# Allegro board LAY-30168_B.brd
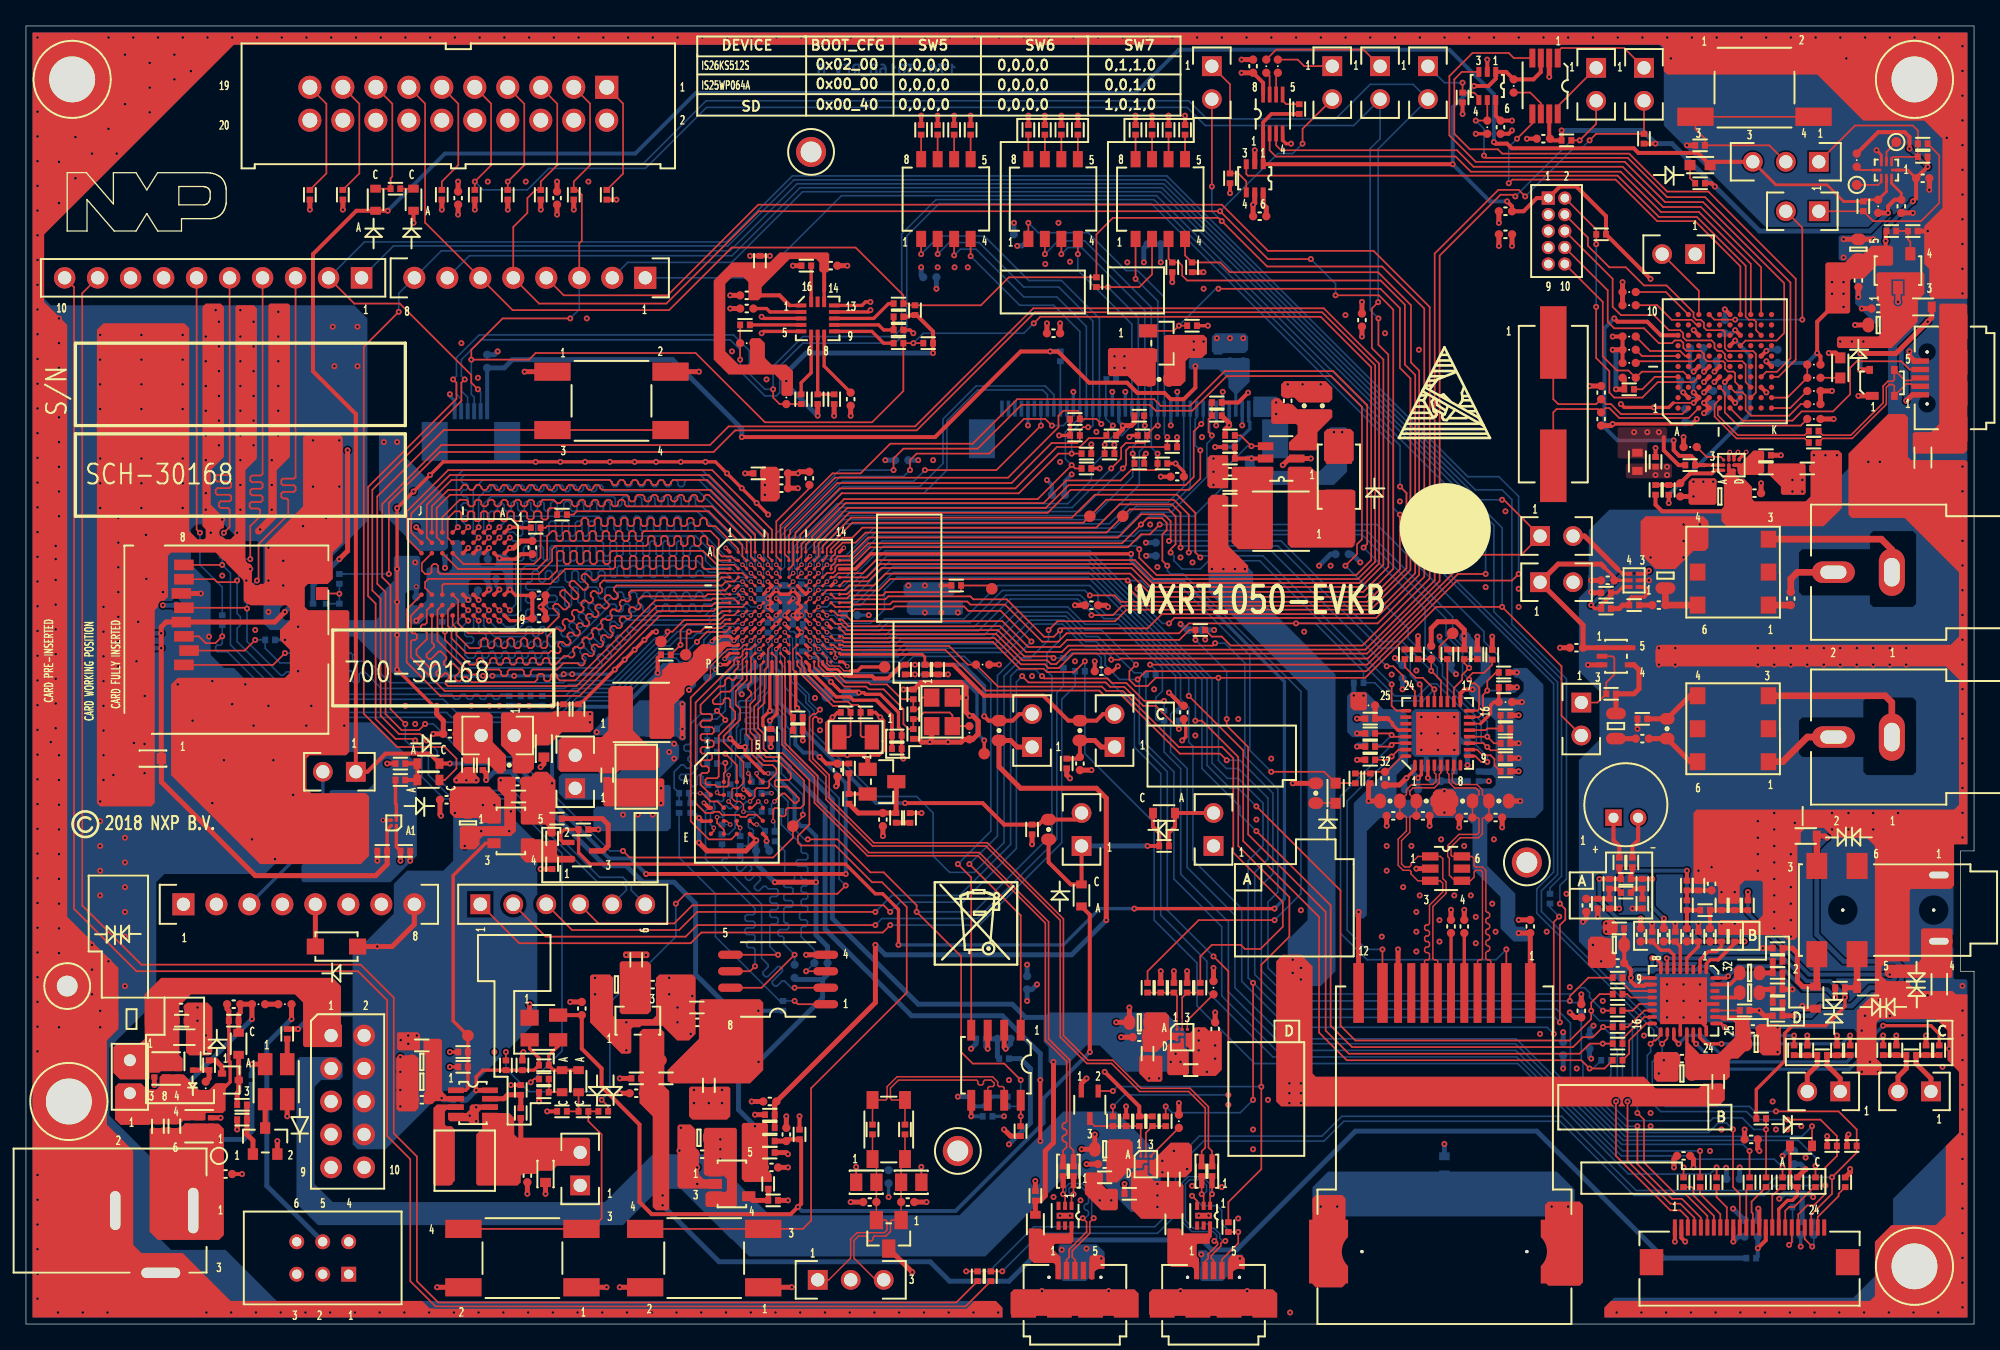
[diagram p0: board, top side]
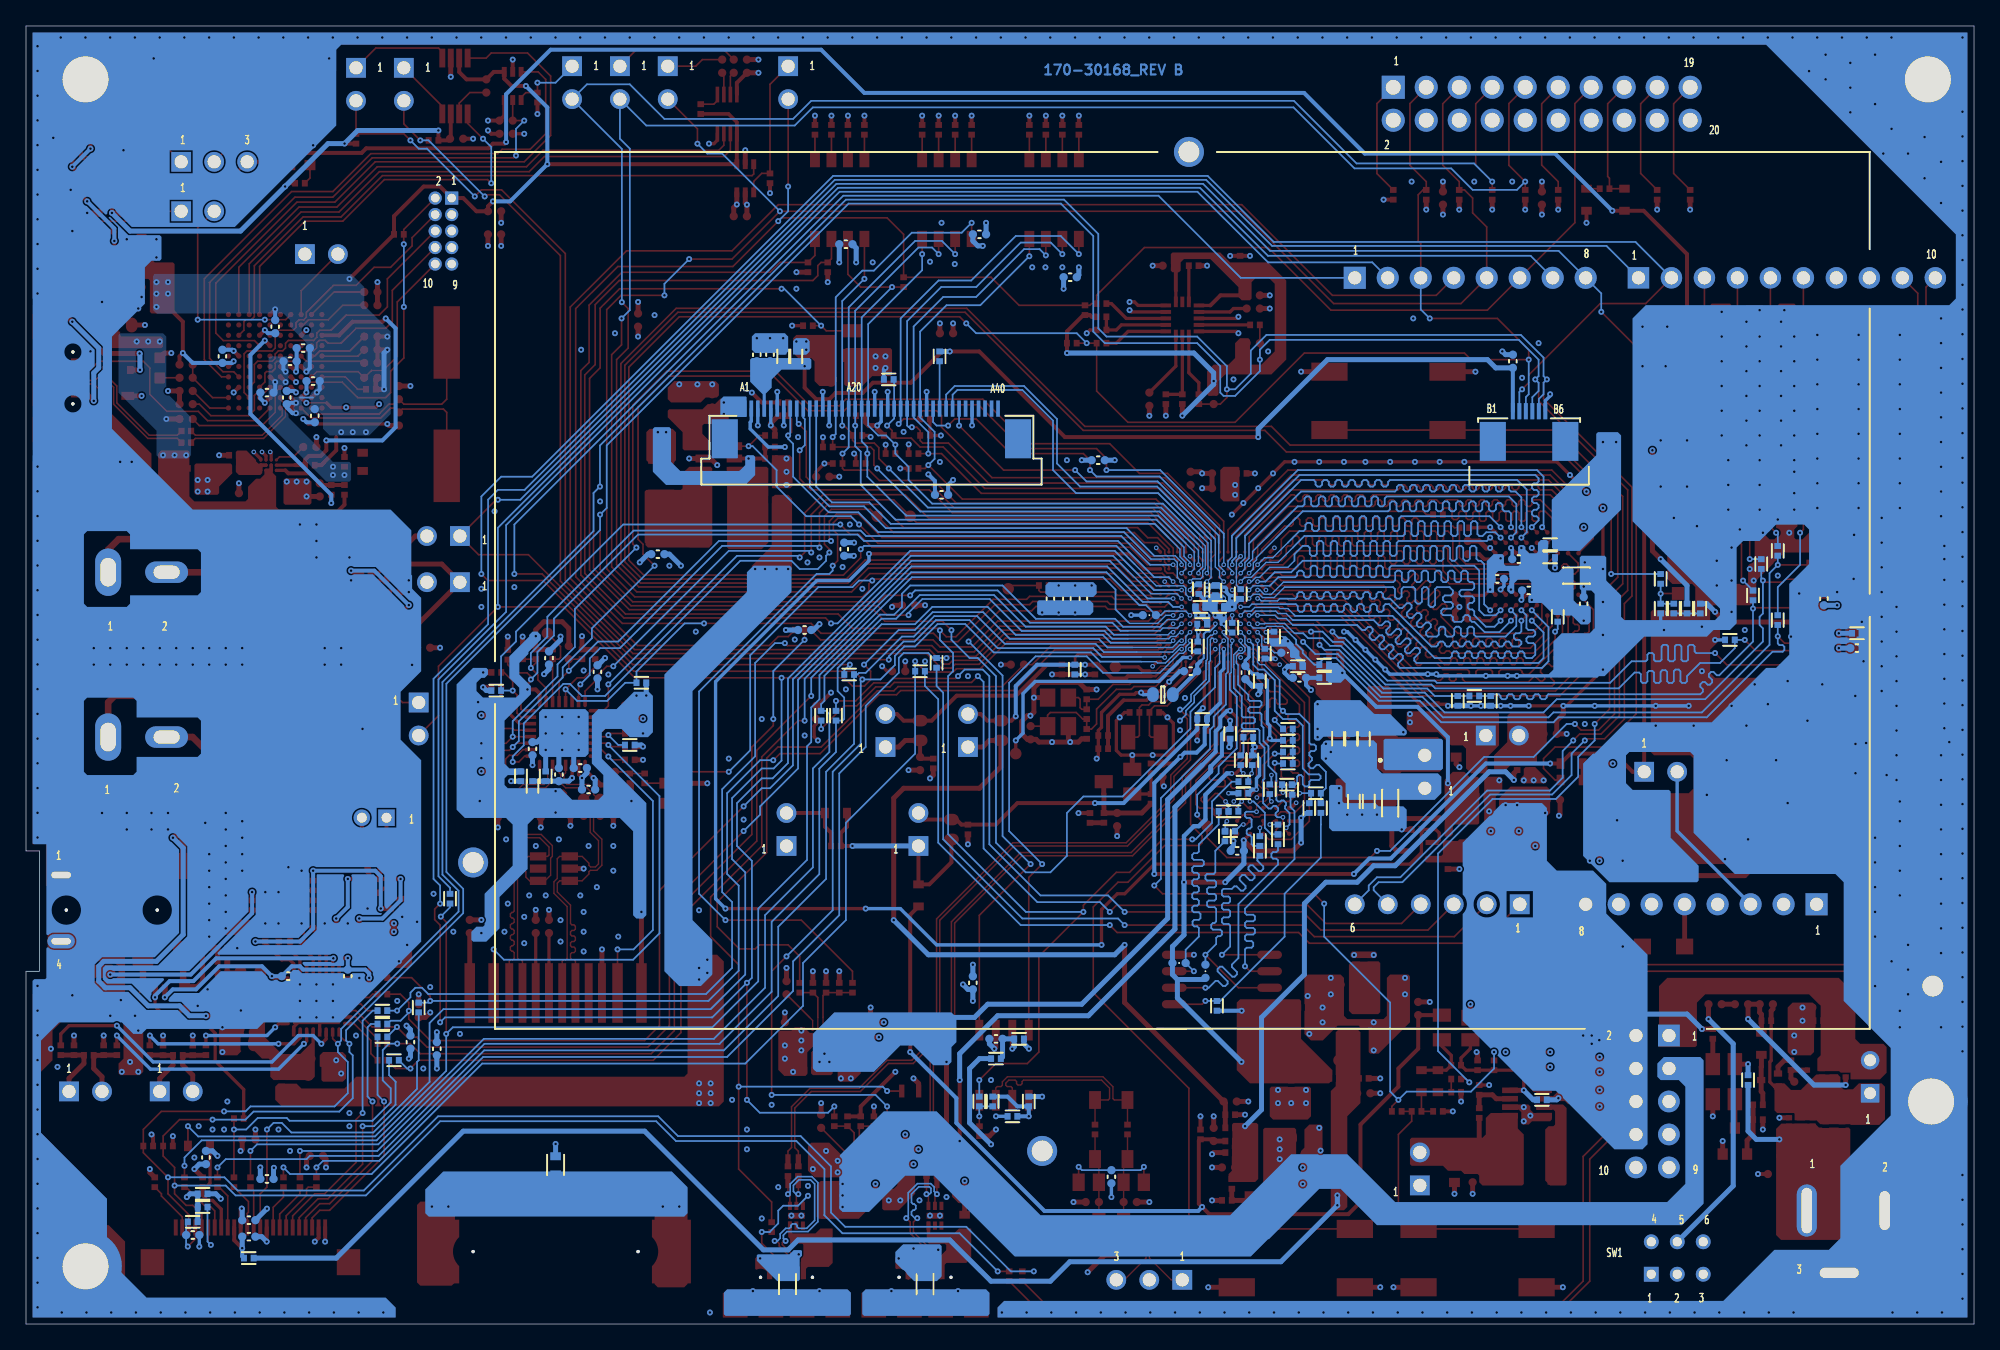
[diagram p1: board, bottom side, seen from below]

Outline 150 x 100 mm; copper layers: TOP, GND, INT1, BOTTOM. Coordinates in mm from the lower left corner of the outline.
Outline path: 0,100 150,100 150,36.45 148.97,36.45 148.97,27.18 150,27.18 150,0 0,0 0,100

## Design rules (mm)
net group CAN1_H: nets CAN1_H N101242461
net group CAN1_L: nets CAN1_L N101242463
net group ENET_RX: nets ENET_RXM ENET_RXP
net group ENET_TX: nets ENET_TXM ENET_TXP
net group FLEXSPI_DQS: nets FLEXSPI_DQS N101481296
net group GPIO_SD_B0_00: nets GPIO_SD_B0_00 N100763722
net group GPIO_SD_B0_02: nets GPIO_SD_B0_02 N100763684
net group GPIO_SD_B0_03: nets GPIO_SD_B0_03 N100763661
net group OTG1_DN: nets N99833038 OTG1_DN
net group OTG1_DP: nets N99833040 OTG1_DP
net group OTG2_DN: nets N99835007 OTG2_DN
net group OTG2_DP: nets N99835017 OTG2_DP
net group SDA_USB_CONN_DM: nets SDA_USB_CONN_DM SDA_USB_DM
net group SDA_USB_CONN_DP: nets SDA_USB_CONN_DP SDA_USB_DP
net group SEMC_CLK: nets N100763780 SEMC_CLK
net group 3W: nets AUD_INT CSI_MCLK CSI_PIXCLK ENET_INT ENET_RST ENET_TX_CLK JTAG_DACK JTAG_NSRST JTAG_RTCK JTAG_TCK LCDIF_CLK SDA_RST_LED SDA_RST_TGTMCU_J_B SW1_RST_B SWD_CLK_TGTMCU_BUF
net group FLEXSPI_CLK: nets FLEXSPI_CLK N100881534 N101474013
net group FLEXSPI_D0_A: nets FLEXSPI_D0_A N100881743 N101474117
net group FLEXSPI_D1_A: nets FLEXSPI_D1_A N100881750 N101474142
net group FLEXSPI_D2_A: nets FLEXSPI_D2_A N100881757 N101474197
net group FLEXSPI_D3_A: nets FLEXSPI_D3_A N100881764 N101474201
net group FLEXSPI_SS0: nets FLEXSPI_SS0 N100881537 N101351285
net group GND: nets GND
net group GPIO_SD_B0_01_B: nets GPIO_SD_B0_01_B N100763741 SD1_CLK
net group POWER: nets CAN_VIO_3V3 FLASH_VCC N99781633 N99781637 SDRAM_3V3 VDD_HIGH_IN_MCU VDD_USB_3V VDDA_ADC_3P3_MCU
net group SPI: nets FLEXSPI_CLK_B FLEXSPI_D0_B FLEXSPI_D1_B FLEXSPI_D2_B FLEXSPI_D3_B

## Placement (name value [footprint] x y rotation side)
C1  0.1UF  [CC0402_25]  11.94 24.38 0 top
C2  1.0UF  [0402_CC]  11.99 23.37 0 top
C3  47uF  [CC1206_OV]  8.13 23.5 180 top
C4  0.1UF  [CC0402_25]  15.37 11.56 0 top
C5  0.01UF  [CC0402_25]  16 24.64 0 top
C6  1.0UF  [0402_CC]  70.23 50.42 270 top
C7  0.22uF  [0402_CC]  69.22 50.42 270 top
C8  0.22uF  [0402_CC]  46.99 45.09 90 bottom
C9  0.22uF  [0402_CC]  58.12 55.24 0 bottom
C10  0.22uF  [0402_CC]  47.75 40.26 270 bottom
C11  0.22uF  [0402_CC]  58.42 56.52 270 bottom
C12  0.22uF  [0402_CC]  59.56 55.24 180 bottom
C13  4.7uF  [0402_CC]  56.46 56.24 90 bottom
C14  22UF  [0603_CC]  44.96 40.13 270 bottom
C15  4.7uF  [0402_CC]  67.69 50.42 270 top
C16  0.22uF  [0402_CC]  69.24 50.42 270 bottom
C17  0.22uF  [0402_CC]  47.96 45.09 90 bottom
C18  0.22uF  [0402_CC]  46.61 40.26 270 bottom
C19  0.22uF  [0402_CC]  59.44 53.92 0 bottom
C20  0.22uF  [0402_CC]  48.97 45.09 90 bottom
C21  0.22uF  [0402_CC]  59.44 45.72 0 top
C22  4.7uF  [0402_CC]  59.44 46.74 0 top
C23  0.22uF  [0402_CC]  77.47 38.1 270 top
C24  0.22uF  [0402_CC]  67.06 45.34 0 top
C25  0.22uF  [0402_CC]  59.77 52.2 90 bottom
C26  4.7uF  [0402_CC]  67.06 44.32 0 top
C27  0.1UF  [CC0402_25]  62.48 42.67 270 top
C29  0.1UF  [CC0402_25]  65.98 38.86 270 top
C30  1.0UF  [0402_CC]  27.43 36.45 180 top
C31  22UF  [0603_CC]  39.88 44.32 270 top
C32  4.7uF  [0402_CC]  52.07 50.67 0 bottom
C33  0.22uF  [0402_CC]  41.4 47.37 90 top
C34  0.22uF  [0402_CC]  42.55 47.37 90 top
C35  0.22uF  [0402_CC]  53.9 52.96 90 bottom
C36  33UF  [CC1210]  46.99 42.16 270 top
C37  0.22uF  [0402_CC]  44.75 42.29 270 top
C39  4.7PF  [0402_CC]  68.33 45.46 270 top
C40  4.7PF  [0402_CC]  68.33 48.51 90 top
C41  0.22uF  [0402_CC]  54.61 51.64 270 bottom
C42  10PF  [0402_CC]  64.64 47.12 0 top
C43  10PF  [0402_CC]  63.12 47.12 180 top
C44  10uF  [CC0603_OV]  30.48 20.19 180 top
C45  10uF  [CC0603_OV]  30.48 18.67 180 top
C46  0.1UF  [CC0402_25]  30.48 17.27 180 top
C47  22UF  [0603_CC]  40.01 11.56 270 top
C48  0.1UF  [CC0402_25]  38.61 11.43 270 top
C49  0.1UF  [CC0402_25]  58.55 14.61 90 top
C50  10uF  [CC0603_OV]  51.82 14.35 180 top
C51  0.1UF  [CC0402_25]  52.07 13.08 180 top
C52  4.7uF  [0402_CC]  57.27 13.21 0 top
C53  0.1UF  [CC0402_25]  57.4 12.06 0 top
C54  0.22uF  [0402_CC]  38.23 19.93 90 top
C55  1000pF  [0402_CC]  33.66 20.95 180 top
C56  1000pF  [0402_CC]  33.66 19.81 180 top
C57  0.1UF  [CC0402_25]  81.15 43.18 270 top
C58  1000pF  [0402_CC]  41.27 16.38 180 top
C59  0.1UF  [CC0402_25]  42.8 24.31 90 top
C60  1.0UF  [0402_CC]  39.88 18.87 0 top
C61  10uF  [CC0603_OV]  34.04 38.61 270 top
C62  0.1UF  [CC0402_25]  32.38 40.39 180 top
C63  4.7uF  [0402_CC]  37.92 40.64 180 top
C64  0.1UF  [CC0402_25]  37.85 41.78 180 top
C65  10uF  [CC0603_OV]  45.47 26.16 180 top
C66  0.1UF  [CC0402_25]  48.26 26.15 0 top
C67  4.7uF  [0402_CC]  46.99 18.92 180 top
C68  0.1UF  [CC0402_25]  46.99 17.78 180 top
C69  0.1UF  [CC0402_25]  58.17 64.39 0 top
C70  0.1UF  [CC0402_25]  58.17 65.53 0 top
C71  4.7uF  [0402_CC]  56.39 65.53 180 top
C72  4.7uF  [0402_CC]  59.69 56.62 270 bottom
C73  0.1UF  [CC0402_25]  71.12 55.88 90 bottom
C74  0.1UF  [CC0402_25]  69.85 55.88 90 bottom
C75  0.1UF  [CC0402_25]  68.58 55.88 90 bottom
C76  0.1UF  [CC0402_25]  60.33 65.15 90 top
C77  4.7uF  [0402_CC]  57.12 53.64 270 bottom
C78  0.1UF  [CC0402_25]  51.94 49.78 0 bottom
C79  1.0UF  [0402_CC]  57.28 45.47 270 bottom
C80  4.7uF  [0402_CC]  54.99 49.53 270 bottom
C81  0.1UF  [CC0402_25]  56.11 50.19 270 bottom
C82  10uF  [CC0603_OV]  62.46 48.49 0 bottom
C83  0.1UF  [CC0402_25]  60.33 50.29 0 bottom
C84  1.0UF  [0402_CC]  57.38 45.47 270 top
C85  4.7uF  [0402_CC]  91.69 74.55 90 bottom
C86  0.1UF  [CC0402_25]  93.73 74.68 90 bottom
C87  0.1UF  [CC0402_25]  92.71 74.68 90 bottom
C88  4.7uF  [0402_CC]  92.71 66.68 180 top
C89  4.7uF  [0402_CC]  92.71 64.64 180 top
C90  0.1UF  [CC0402_25]  92.71 65.66 180 top
C91  0.1UF  [CC0402_25]  97.16 71.12 90 top
C92  0.1UF  [CC0402_25]  35.51 74.17 90 bottom
C93  4.7uF  [0402_CC]  88.39 11.15 90 top
C97  4.7uF  [0402_CC]  77.72 9.88 90 top
C98  0.1UF  [CC0402_25]  75.31 21.97 0 bottom
C99  1.0UF  [0402_CC]  73.53 21.97 180 bottom
C100  1.0UF  [0402_CC]  74.04 16 0 bottom
C101  56PF  [CC0402_25]  64.97 9.4 0 top
C102  0.01UF  [CC0402_25]  66.42 11.35 270 bottom
C103  56PF  [CC0402_25]  67.89 9.4 0 top
C104  10uF  [CC0603_OV]  122.3 29.21 180 top
C105  0.1UF  [CC0402_25]  122.56 27.81 180 top
C106  0.1UF  [CC0402_25]  125.22 26.8 270 bottom
C107  0.1UF  [CC0402_25]  129.79 26.8 180 bottom
C108  10uF  [CC0603_OV]  127.51 19.3 180 top
C109  10uF  [CC0603_OV]  133.22 21.59 0 top
C110  0.1UF  [CC0402_25]  127.51 20.45 180 top
C111  0.1UF  [CC0402_25]  132.97 22.73 0 top
C112  4.7uF  [0402_CC]  131.57 29.84 90 top
C113  4.7uF  [0402_CC]  132.33 24.15 0 top
C114  220PF  [0402_CC]  134.87 28.96 0 top
C115  220PF  [0402_CC]  134.87 23.75 180 top
C116  4.7uF  [0402_CC]  121.03 32.38 270 top
C117  0.1UF  [CC0402_25]  120.14 32.25 270 top
C118  15PF  [0402_CC]  125.22 29.84 270 top
C119  4.7uF  [0402_CC]  128.78 33.78 90 top
C120  0.1UF  [CC0402_25]  129.79 33.92 90 top
C121  15PF  [0402_CC]  128.78 29.84 270 top
C122  0.1UF  [CC0402_25]  124.33 29.98 270 top
C123  0.1UF  [CC0402_25]  127.89 29.98 90 top
C124  4.7uF  [0402_CC]  123.19 33.24 0 top
C125  0.1UF  [CC0402_25]  129.67 29.98 90 top
C126  0.1UF  [CC0402_25]  126.11 29.98 270 top
C127  15PF  [0402_CC]  130.56 29.84 90 top
C128  15PF  [0402_CC]  130.56 32.26 90 top
C129  15PF  [0402_CC]  131.57 32.26 90 top
C130  15PF  [0402_CC]  127 29.84 90 top
C131  0.1UF  [CC0402_25]  135.89 55.89 270 top
C132  0.01UF  [CC0402_25]  125.73 55.38 180 top
C133  0.1UF  [CC0402_25]  121.79 57.29 180 top
C134  15PF  [0402_CC]  146.3 21.09 270 top
C135  15PF  [0402_CC]  139.45 21.08 270 top
C136  15PF  [0402_CC]  144.02 21.09 90 top
C137  15PF  [0402_CC]  137.16 21.08 90 top
C138  0.1UF  [CC0402_25]  119.39 52.1 180 top
C139  0.1UF  [CC0402_25]  124.46 45.1 0 top
C140  4.7uF  [0402_CC]  109.98 42.2 90 bottom
C141  0.1UF  [CC0402_25]  108.97 42.33 90 bottom
C142  2.2uF  [CC0402_25]  107.31 42.83 0 bottom
C143  0.1UF  [CC0402_25]  106.68 41.18 180 bottom
C144  10PF  [CC0402_25]  113.16 39.02 0 top
C145  10PF  [CC0402_25]  110.87 39.02 180 top
C146  10PF  [CC0402_25]  107.57 39.15 0 top
C147  10PF  [CC0402_25]  105.28 39.15 180 top
C148  0.1UF  [CC0402_25]  115.83 30.63 90 top
C149  0.1UF  [CC0402_25]  109.73 30.63 90 top
C150  0.1UF  [CC0402_25]  110.75 30.63 90 top
C160  4.7uF  [0402_CC]  9.02 53.21 180 bottom
C161  0.1UF  [CC0402_25]  9.02 52.07 180 bottom
C162  0.1UF  [CC0402_25]  56.73 36.45 0 bottom
C163  4.7uF  [0402_CC]  56.26 40.89 0 bottom
C164  4.7uF  [0402_CC]  32.64 59.05 180 bottom
C165  0.1UF  [CC0402_25]  38.99 59.82 90 top
C166  0.1UF  [CC0402_25]  35.05 58.93 0 bottom
C167  0.1UF  [CC0402_25]  39.5 56.13 0 top
C168  0.1UF  [CC0402_25]  36.7 57.4 180 bottom
C169  0.1UF  [CC0402_25]  39.5 54.36 0 top
C170  0.1UF  [CC0402_25]  34.29 56.52 0 bottom
C171  0.1UF  [CC0402_25]  30.06 55.5 90 bottom
C184  10uF  [CC0603_OV]  130.43 63.75 180 top
C185  0.1UF  [CC0402_25]  133.1 64.01 0 top
C186  0.1UF  [CC0402_25]  113.92 85.72 180 top
C187  0.1UF  [CC0402_25]  61.97 81.53 0 top
C188  0.1UF  [CC0402_25]  55.5 79.25 180 top
C189  0.1UF  [CC0402_25]  63.5 71.25 270 top
C190  0.1UF  [CC0402_25]  55.5 78.23 180 top
C191  1.0UF  [0402_CC]  51.66 24.38 180 top
C192  0.1UF  [CC0402_25]  51.69 23.24 180 top
C193  0.1UF  [CC0402_25]  111 44.32 90 bottom
C194  0.1UF  [CC0402_25]  120.4 21.72 90 bottom
C195  0.1UF  [CC0402_25]  118.36 21.21 90 bottom
C196  0.1UF  [CC0402_25]  119.76 24.13 90 top
C197  0.1UF  [CC0402_25]  90.04 53.47 180 bottom
C198  0.1UF  [CC0402_25]  82.8 50.29 0 top
C199  0.1UF  [CC0402_25]  89.15 47.12 270 top
C200  0.1UF  [CC0402_25]  91.57 22.73 270 top
C201  0.1UF  [CC0402_25]  77.09 26.29 270 bottom
C202  0.1UF  [CC0402_25]  131.44 11.18 180 bottom
C203  0.1UF  [CC0402_25]  127.64 12.95 180 top
C204  0.1UF  [CC0402_25]  132.84 14.22 0 top
C205  0.1UF  [CC0402_25]  136.14 12.83 90 bottom
C206  0.1UF  [CC0402_25]  113.92 83.95 0 top
C207  0.1UF  [CC0402_25]  40.89 86.74 270 top
C208  0.1UF  [CC0402_25]  102.87 77.34 270 top
C209  0.1UF  [CC0402_25]  33.27 86.74 270 top
C210  0.1UF  [CC0402_25]  109.73 51.31 270 bottom
C211  0.1UF  [CC0402_25]  105.99 50.24 270 bottom
C212  0.1UF  [CC0402_25]  82.04 55.37 0 top
C213  0.1UF  [CC0402_25]  76.58 83.95 180 bottom
C214  0.1UF  [CC0402_25]  69.6 80.64 180 bottom
C215  0.1UF  [CC0402_25]  86.87 83.19 180 bottom
C216  0.1UF  [CC0402_25]  79.12 76.33 180 top
C217  0.1UF  [CC0402_25]  101.35 59.31 0 bottom
C218  0.1UF  [CC0402_25]  67.44 66.55 180 bottom
C219  0.1UF  [CC0402_25]  87 59.69 90 bottom
C220  0.1UF  [CC0402_25]  88.65 65.28 0 top
C221  0.1UF  [CC0402_25]  79.5 63.88 180 bottom
C222  0.1UF  [CC0402_25]  11.56 55.88 90 bottom
C223  0.1UF  [CC0402_25]  32.64 45.47 180 top
C229  0.1UF  [CC0402_25]  57.28 17.14 180 top
C230  22UF  [CC0603_OV]  132.72 27.05 0 top
C231  22UF  [CC0603_OV]  132.72 25.53 0 top
C232  15PF  [0402_CC]  145.16 20.7 180 top
C233  15PF  [0402_CC]  138.3 20.7 180 top
C234  0.1UF  [CC0402_25]  104.65 42.04 270 top
C235  10uF  [CC0603_OV]  83.06 13.46 180 top
C236  0.1UF  [CC0402_25]  83.06 12.32 180 top
C237  10uF  [CC0603_OV]  85.72 23.24 180 top
C238  0.1UF  [CC0402_25]  85.72 22.1 180 top
C239  4.7uF  [0402_CC]  89.69 19.56 0 top
C240  4.7uF  [0402_CC]  84.96 10.03 180 top
C241  4.7uF  [0402_CC]  133.99 66.93 0 top
C242  22UF  [0603_CC]  9.78 43.56 180 top
C243  22UF  [0603_CC]  30.61 57.66 180 bottom
C244  18PF  [0402_CC]  39.75 48.01 270 bottom
C245  18PF  [0402_CC]  37.21 48.01 270 bottom
C246  0.1UF  [CC0402_25]  132.84 8 180 bottom
C247  0.1UF  [CC0402_25]  132.84 6.73 180 bottom
C248  0.1UF  [CC0402_25]  137.16 6.86 180 bottom
C249  4.7uF  [0402_CC]  136.4 10.03 180 bottom
C252  1.0UF  [0402_CC]  29.21 36.45 0 top
C254  0.1UF  [CC0402_25]  129.67 74.17 180 bottom
C255  10uF  [CC0603_OV]  141.1 82.8 90 top
C257  10uF  [CC0603_OV]  142.62 76.96 180 top
C258  4.7uF  [0402_CC]  125.48 66.42 90 top
C259  0.1UF  [CC0402_25]  142.62 78.23 180 top
C260  0.1UF  [CC0402_25]  141.1 80.39 270 top
C261  0.1UF  [CC0402_25]  131.44 71.75 0 bottom
C262  0.1UF  [CC0402_25]  127.89 72.64 0 bottom
C263  0.1UF  [CC0402_25]  134.87 74.55 90 bottom
C264  0.1UF  [CC0402_25]  130.81 76.83 270 bottom
C265  0.1UF  [CC0402_25]  129.92 71.37 90 bottom
C266  2.2uF  [CC0402_25]  128.65 75.18 0 bottom
C267  2.2uF  [CC0402_25]  127.76 69.98 270 bottom
C268  0.1UF  [CC0402_25]  144.4 86.11 270 top
C270  0.1UF  [CC0402_25]  146.05 88.27 0 top
C272  1000pF  [0402_CC]  128.91 90.81 180 top
C273  27PF  [CC0402_25]  121.28 69.72 270 top
C274  27PF  [CC0402_25]  121.28 71.75 90 top
C275  0.1UF  [CC0402_25]  116.84 91.31 180 top
C276  0.1UF  [CC0402_25]  113.54 92.2 270 top
C277  0.1UF  [CC0402_25]  94.49 96.9 90 top
C278  0.1UF  [CC0402_25]  95 85.34 180 top
D1  MM5Z5V1ST1G  [SOD_523_1P4]  12.83 20.26 90 top
D2  RB521S30  [SOD523]  16.37 21.59 270 top
D3  LED_RED-GRN  [LED_DUAL_3025MM_SM]  19.26 18.67 270 top
D4  RB521S30  [SOD523]  81.27 33.02 270 top
D5  RB521S30  [SOD523]  87.63 39.36 0 top
D6  RB521S30  [SOD523]  30.99 41.91 180 top
D7  RB521S30  [SOD523]  30.99 43.18 180 top
D8  RB521S30  [SOD523]  42.55 18.71 90 top
D9  RB521S30  [SOD523]  41.28 18.71 90 top
D10  MBRA160T3G  [CASE403D_02]  101.09 65.28 270 top
D11  NUP2105L  [SOT-23]  66.43 6.91 180 top
D12  RB521S30  [SOD523]  29.84 86.61 270 top
D13  RB521S30  [SOD523]  26.92 86.61 270 top
D14  MBR120VLSFT1G  [SOD-123]  23.91 29.08 180 top
D17  RB521S30  [SOD523]  136.68 13.72 180 top
D18  GREEN  [LED_0603]  100.84 40.89 90 top
D20  RED  [LED_0603]  139.7 73.66 90 top
D21  RED  [LED_0603]  128.91 89.28 0 top
FL1  ACT45B-510-2P  [IND4_4P7X3P4_SMT]  66.43 14.99 90 top
H1  .635" LONG  [SPACER_139T]  3.56 95.89 0 top
H2  .635" LONG  [SPACER_139T]  145.41 95.89 0 top
H3  .635" LONG  [SPACER_139T]  3.3 17.14 0 top
H4  .635" LONG  [SPACER_139T]  145.41 4.45 270 top
J1  HDR 2X5  [HDR205]  23.5 22.23 0 top
J2  CON_1_PWR  [CON3_PWR_TH]  12.88 8.74 270 top
J3  HDR 1X2  [HDR102]  83.82 44.45 180 top
J4  HDR 1X2  [HDR102]  77.47 44.45 180 top
J5  HDR 1X2  [HDR102]  81.28 36.83 180 top
J6  HDR 1X2  [HDR102]  91.44 36.83 180 top
J7  HDR 1X2  [HDR102]  42.67 10.68 180 top
J8  CON 1X40 + CON 1X6 + TFT DISPLAY  [MODULE_TOUCH_PANEL_46P]  60.96 56.52 180 bottom
J9  USB_MICROAB_RECEPTACLE  [CON_USB5_MICROAB_0P65_SM]  91.44 1.48 0 top
J10  USB_MICROAB_RECEPTACLE  [CON_USB5_MICROAB_0P65_SM]  80.77 1.48 0 top
J11  HDR_1X3  [HDR103]  60.97 3.4 90 top
J12  PJ31360-I  [CON6_AUDJACK_RA_TH]  147.3 34.59 180 top
J13  HDR 1X2  [HDR102]  116.59 57.15 90 top
J14  CON_2_RCA  [CON2_RCA_RA_TH]  143.67 57.92 180 top
J15  HDR 1X2  [HDR102]  116.59 60.71 90 top
J16  HDR 1X2  [HDR102]  146.69 17.92 270 top
J17  HDR 1X2  [HDR102]  139.7 17.92 270 top
J18  CON_2_RCA  [CON2_RCA_RA_TH]  143.67 45.22 180 top
J19  RJ45_YLW+GRN  [CON12_RJ45_1P02_SM]  109.22 15.54 180 top
J21  BH25420B301  [HDR_2X10M_100_TH]  44.72 95.28 270 top
J22  SKT_1X8  [CON_1X8_SKT_2P54_TH]  47.68 80.6 270 top
J23  SKT_1X6  [CON_SKT1X6_TH]  34.98 32.34 90 top
J24  SKT_1X10  [CON_SKT1X10_TH]  25.84 80.6 270 top
J25  SKT_1X8  [CON_1X8_SKT_2P54_TH]  12.12 32.34 90 top
J26  HDR 1X2  [HDR102]  25.4 42.55 270 top
J34  HDR 2X5  [HDR205_50_TH]  117.22 86.74 270 top
J35  CON_1X24  [FPC1X24_0P5_16P6X5P35]  132.72 4.26 0 top
J36  HDR 1X2  [HDR102]  42.29 41.27 180 top
J37  HDR 1X2  [HDR102]  37.59 45.34 270 top
J38  HDR 1X2  [HDR102]  119.76 47.88 0 top
J39  95220030-14RRF  [CON_SDCARD_95220]  15.43 52.72 90 top
J41  USB_MICROAB_RECEPTACLE  [CON_USB5_MICROAB_0P65_SM]  148.5 72.89 90 top
J42  HDR 1X2  [HDR102]  128.52 82.42 270 top
J43  HDR_1X3  [HDR103]  138.05 89.53 270 top
J44  HDR 1X2  [HDR102]  138.05 85.72 270 top
J45  HDR 1X2  [HDR102]  120.9 96.77 0 top
J46  HDR 1X2  [HDR102]  124.59 96.77 0 top
J47  HDR 1X2  [HDR102]  107.95 96.9 0 top
J48  HDR 1X2  [HDR102]  104.27 96.9 0 top
J49  HDR 1X2  [HDR102]  100.58 96.9 0 top
J50  HDR 1X2  [HDR102]  91.31 96.9 0 top
JP1  SHORT_100mil  [100MIL_TH]  8 17.78 90 top
L1  4.7uH  [IND_VLS4012E]  47.37 47.12 0 top
L2  1uH  [IND_4020]  33.78 12.59 0 top
L3  10uH  [IND_VLS4012E]  96.65 61.85 180 top
L4  330 OHM  [IND_1608]  88.39 7.72 90 top
L5  90OHM  [IND4_CHOKE_0805]  90.93 11.77 90 top
L6  330 OHM  [IND_1608]  91.36 3.1 90 bottom
L7  330 OHM  [IND_1608]  77.72 7.72 90 top
L8  90OHM  [IND4_CHOKE_0805]  80.26 11.77 90 top
L9  330 OHM  [IND_1608]  80.77 3.1 90 bottom
L10  120 Ohm  [0402_CC]  134.87 27.94 0 top
L11  120 Ohm  [0402_CC]  134.87 24.77 0 top
L12  120 Ohm  [0402_CC]  132.59 32.26 90 top
L13  120 Ohm  [0402_CC]  111 41.45 90 bottom
L14  330 OHM  [IND_1608]  109.22 12.22 270 bottom
L17  120 Ohm  [0402_CC]  140.08 10.92 90 top
L18  120 Ohm  [0402_CC]  32.64 60.07 0 bottom
L19  120 Ohm  [0402_CC]  137.16 7.87 180 bottom
L20  120 Ohm  [0402_CC]  132.84 5.08 0 bottom
L22  330 OHM  [IND_1608]  146.06 66.71 270 top
L23  330 OHM  [IND_1608]  146.05 78.36 180 top
L24  330 OHM  [IND_1608]  124.08 66.42 270 top
NOREF  -  []  10.38 3.94 0 top
NOREF#2  -  []  29.6 53.73 0 top
NOREF#3  -  []  62.46 75.97 90 top
NOREF#4  -  []  8.32 46.12 0 top
NOREF#5  -  []  59.46 75.97 0 top
NOREF#6  -  []  8.32 46.12 0 top
NOREF#7  -  []  23.1 45.64 90 top
NOREF#8  -  []  43.11 64.84 0 top
NOREF#9  -  []  62.24 76.47 90 top
NOREF#10  -  []  31.47 68 0 top
NOREF#11  -  []  33.01 70.32 0 top
NOREF#12  -  []  141.96 73.5 0 top
NOREF#13  -  []  28.12 38.41 90 top
NOREF#14  -  []  8.32 46.12 90 top
NOREF#15  -  []  150 0 0 top
NOREF#16  -  []  86.63 11.72 90 top
NOREF#17  -  []  86.63 11.72 90 top
NOREF#18  -  []  148.95 0 90 top
NOREF#19  -  []  -0.21 0 0 top
NOREF#20  -  []  62.24 76.47 90 top
NOREF#21  -  []  117.16 35.56 0 top
NOREF#22  -  []  12.56 51.88 90 top
NOREF#23  -  []  146.9 31.89 90 top
NOREF#24  -  []  142.53 89.53 0 top
NOREF#25  -  []  113.71 22.92 90 top
NOREF#26  -  []  45.9 47.12 0 top
NOREF#27  -  []  23.62 47.62 0 top
NOREF#28  -  []  150 0 90 top
NOREF#29  -  []  73.61 68.2 0 top
NOREF#30  -  []  99.62 0.18 90 top
NOREF#31  -  []  94.98 59.8 90 top
NOREF#32  -  []  54.19 51.02 0 top
NOREF#33  -  []  24.4 95.28 0 top
NOREF#34  -  []  85.54 11.48 0 top
NOREF#35  -  []  142.16 71.5 0 top
NOREF#36  -  []  117.22 81.66 90 top
NOREF#37  -  []  43.42 50.25 0 top
NOREF#38  -  []  46.78 60.89 90 top
NOREF#39  -  []  43.42 40.25 90 top
NOREF#40  -  []  61.46 76.19 90 top
NOREF#41  -  []  132.16 64.1 90 top
NOREF#42  -  []  69.98 27.69 0 top
NOREF#43  -  []  89.43 21.5 90 top
NOREF#44  -  []  62.04 90.3 0 top
NOREF#45  -  []  -0.77 13.34 0 top
NOREF#46  -  []  102.61 25.5 0 top
NOREF#47  -  []  131.52 66.57 0 top
NOREF#48  -  []  0 0 90 top
NOREF#49  -  []  116.08 87.57 0 top
NOREF#50  -  []  22.52 51.97 90 top
NOREF#51  -  []  21.86 92.74 90 top
NOREF#52  -  []  86.92 11.48 90 top
NOREF#53  -  []  31.47 68 90 top
NOREF#54  -  []  141 28.49 0 top
NOREF#55  -  []  22.52 57.67 90 top
NOREF#56  -  []  59.68 76.47 0 top
NOREF#57  -  []  21.86 95.28 0 top
NOREF#58  -  []  102.87 5.58 90 top
NOREF#59  -  []  147.3 29.49 90 top
NOREF#60  -  []  0 0.03 0 top
NOREF#61  -  []  49.04 45.07 90 top
NOREF#62  -  []  109.66 62.14 0 top
NOREF#63  -  []  94.6 63.52 0 top
NOREF#64  -  []  116.08 80.84 90 top
NOREF#65  -  []  143.46 88.28 90 top
NOREF#66  -  []  0 0 0 top
NOREF#67  -  []  99.62 0.18 0 top
NOREF#68  -  []  117.22 85.47 90 top
NOREF#69  -  []  12.88 8.74 90 top
NOREF#70  -  []  132.16 64.1 0 top
NOREF#71  -  []  113.71 -44.28 90 top
NOREF#72  -  []  30.51 69.59 90 top
NOREF#73  -  []  131.92 65.77 90 top
NOREF#74  -  []  73.34 13.34 0 top
NOREF#75  -  []  142.51 88.9 90 top
NOREF#76  -  []  105.65 25.5 0 top
NOREF#77  -  []  62.24 76.47 90 top
NOREF#78  -  []  26.05 56.19 90 top
NOREF#79  -  []  96.19 68.2 90 top
NOREF#80  -  []  60.46 76.19 0 top
NOREF#81  -  []  102.61 25.5 0 top
NOREF#82  -  []  108.53 71.26 0 top
NOREF#83  -  []  37.02 66.49 0 top
NOREF#84  -  []  101.05 25.83 0 top
NOREF#85  -  []  3.81 69.22 0 top
NOREF#86  -  []  46.63 65.84 90 top
NOREF#87  -  []  98.8 27.95 0 top
NOREF#88  -  []  104.45 25.5 0 top
NOREF#89  -  []  22.8 56.28 90 top
NOREF#90  -  []  143.39 34.69 0 top
NOREF#91  -  []  94.15 70.52 0 top
NOREF#92  -  []  139.9 31.89 0 top
NOREF#93  -  []  7.75 45.64 0 top
NOREF#94  -  []  137.9 28.49 0 top
NOREF#95  -  []  10.38 3.94 90 top
NOREF#96  -  []  143.39 34.69 90 top
NOREF#97  -  []  137.9 28.49 90 top
NOREF#98  -  []  75.15 70.52 0 top
NOREF#99  -  []  8.32 46.12 90 top
NOREF#100  -  []  -0.77 13.34 90 top
NOREF#101  -  []  27.92 38.21 90 top
NOREF#102  -  []  89.72 21.26 90 top
NOREF#103  -  []  113.99 25.5 0 top
NOREF#104  -  []  54.19 51.02 0 top
NOREF#105  -  []  6.88 8.74 90 top
NOREF#106  -  []  112.79 25.5 0 top
NOREF#107  -  []  130.72 66.57 0 top
NOREF#108  -  []  27.92 39.01 0 top
NOREF#109  -  []  7.75 45.64 0 top
NOREF#110  -  []  8.32 46.12 0 top
NOREF#111  -  []  23.1 45.64 90 top
NOREF#112  -  []  88.63 21.5 0 top
NOREF#113  -  []  62.44 78.97 0 top
NOREF#114  -  []  4.57 38.48 0 top
NOREF#115  -  []  143.26 89.55 0 top
NOREF#116  -  []  88.63 21.5 0 top
NOREF#117  -  []  143.39 34.69 0 top
NOREF#118  -  []  60.46 76.19 90 top
NOREF#119  -  []  8.32 46.12 0 top
NOREF#120  -  []  45.32 45.45 0 top
NOREF#121  -  []  95.17 61.85 0 top
NOREF#122  -  []  85.83 11.72 0 top
NOREF#123  -  []  16.78 89.21 0 top
NOREF#124  -  []  100.3 5.58 0 top
NOREF#125  -  []  11.96 54.08 0 top
NOREF#126  -  []  4.76 26.04 0 top
NOREF#127  -  []  22.52 57.67 90 top
NOREF#128  -  []  3.81 62.23 0 top
NOREF#129  -  []  12.16 50.78 90 top
NOREF#130  -  []  85.83 11.72 0 top
NOREF#131  -  []  102.87 5.58 0 top
NOREF#132  -  []  35.01 70.32 0 top
NOREF#133  -  []  143.39 34.69 0 top
NOREF#134  -  []  143.39 47.54 0 top
NOREF#135  -  []  117.22 86.74 0 top
NOREF#136  -  []  113.71 22.92 0 top
NOREF#137  -  []  28.12 38.41 0 top
NOREF#138  -  []  8.32 46.12 0 top
NOREF#139  -  []  131.92 65.77 90 top
NOREF#140  -  []  88.34 21.26 0 top
NOREF#141  -  []  89.43 21.5 90 top
NOREF#142  -  []  43.5 40.25 0 top
NOREF#143  -  []  31.47 68 90 top
P1  EM6022P  [MIC_WM-63PR]  122.24 39.01 270 top
Q1  FDMA530PZ  [MLP6_2X2MM_SLUG]  13.34 15.24 180 top
Q2  FDMA530PZ  [MLP6_2X2MM_SLUG]  10.79 19.68 0 top
Q3  MMBT3906TT1G  [SC_75]  15.74 18.8 270 top
Q4  BSH111BK  [SOT23_A]  18.41 14.1 0 top
Q6  IRLML6401  [SOT-23]  87.5 75.56 270 top
Q9  2SK3018  [SOT323_3]  42.8 36.45 270 top
Q15  2SK3018  [SOT323_3]  81.92 16.89 180 top
R1  0  [0402_CC]  10.16 15.24 90 top
R2  0  [0402_CC]  11.43 15.24 90 top
R3  3.3K  [RC0402_25]  13.84 18.16 90 top
R4  100K  [0402_CC]  16 23.37 0 top
R5  10K  [0402_CC]  14.1 19.94 90 top
R6  1K  [0402_CC]  17.4 18.8 90 bottom
R7  1K  [0402_CC]  20.11 22.35 270 top
R8  2.2K  [RC0402_25]  17.91 24.64 0 top
R9  3.3K  [RC0402_25]  19.94 24.64 0 top
R10  10K  [0402_CC]  16.64 16.89 0 top
R11  100K  [0402_CC]  16.64 15.75 180 top
R12  0.02  [RC0603_OV]  81.15 45.72 90 top
R13  0.02  [RC0603_OV]  45.72 43.43 180 bottom
R14  0.02  [RC0603_OV]  74.93 45.72 90 top
R15  0.02  [RC0603_OV]  78.74 38.1 90 top
R16  1K  [0402_CC]  87.63 36.83 180 top
R18  1.5K  [0402_CC]  67 39 90 top
R19  0  [0402_CC]  63.37 40.46 90 top
R20  0  [0402_CC]  63.37 42.81 90 top
R21  100K  [0402_CC]  59.44 46.61 180 bottom
R24  0.02  [RC0603_OV]  87.25 72.77 0 top
R25  0  [0402_CC]  34.04 43.05 90 top
R27  10K  [0402_CC]  28.83 43.18 0 top
R28  1M  [0402_CC]  68.33 46.98 90 top
R29  0  [0402_CC]  28.83 41.91 180 top
R30  2.2M  [RC0402_25]  72.64 45.55 270 top
R31  10K  [0402_CC]  89.79 76.91 0 top
R32  30K  [RC0402_25]  52.83 51.71 0 bottom
R33  0  [0402_CC]  30.48 21.46 0 top
R34  0  [0402_CC]  57.28 14.1 0 top
R35  100K  [0402_CC]  33.27 17.27 0 bottom
R36  180K  [0402_CC]  38.1 16.26 90 top
R38  10K  [0402_CC]  36.96 19.93 90 top
R39  40.2K  [0402_CC]  38.1 18.03 90 top
R41  0  [0402_CC]  39.88 19.94 180 top
R42  0  [0402_CC]  35.18 43.05 90 top
R43  100  [0402_CC]  42.92 16.38 180 top
R44  0  [0402_CC]  80.14 43.18 90 top
R45  1M  [0402_CC]  39.88 17.86 180 top
R46  464K  [0402_CC]  40.51 37.41 270 top
R47  243K  [0402_CC]  40.89 38.94 0 top
R48  0  [0402_CC]  46.99 28.05 270 top
R49  0  [0402_CC]  49.28 18.92 0 top
R52  200K  [0402_CC]  40.51 35.42 270 top
R54  100K  [0402_CC]  42.93 38.1 0 top
R55  4.7K  [RC0402_25]  63.5 54.61 180 bottom
R57  4.7K  [RC0402_25]  73.66 50.8 180 top
R59  10K  [0402_CC]  50.04 50.8 0 bottom
R60  10K  [0402_CC]  49.27 51.56 0 top
R61  0  [0402_CC]  50.04 49.78 0 bottom
R62  0  [0402_CC]  90.68 74.55 270 bottom
R63  0  [0402_CC]  92.71 67.56 180 top
R64  0  [0402_CC]  92.71 63.5 0 top
R65  10  [RC0603_OV]  98.42 70.74 90 top
R66  10  [RC0603_OV]  99.82 70.74 90 top
R67  10K  [0402_CC]  79.65 74.55 270 bottom
R68  0  [0402_CC]  91.33 11.77 90 top
R69  0  [0402_CC]  90.53 11.77 90 top
R71  0  [0402_CC]  92.58 7.47 90 top
R83  0  [0402_CC]  80.66 11.77 90 top
R84  0  [0402_CC]  79.86 11.77 90 top
R85  0  [0402_CC]  75.31 20.45 180 bottom
R86  0  [0402_CC]  72.78 17.14 90 bottom
R87  0  [0402_CC]  65.18 14.99 270 top
R88  62.0  [0805_CC]  64.7 10.92 180 top
R89  62.0  [0805_CC]  68.16 10.92 180 top
R90  10K  [0402_CC]  75.56 17.14 270 bottom
R91  0  [0402_CC]  67.68 14.99 270 top
R92  0  [0402_CC]  76.59 17.14 270 bottom
R93  0  [0402_CC]  122.68 30.48 0 top
R94  100K  [0402_CC]  139.69 25.91 0 top
R95  0  [0402_CC]  130.3 18.67 90 top
R96  0  [0402_CC]  122.56 21.6 0 top
R97  10K  [0402_CC]  134.87 27.05 180 top
R98  0  [0402_CC]  122.56 24.14 0 top
R99  0  [0402_CC]  122.56 25.41 0 top
R100  0  [0402_CC]  122.56 20.32 0 top
R101  0  [0402_CC]  122.56 22.88 0 top
R102  0  [0402_CC]  122.56 26.68 0 top
R103  10K  [0402_CC]  134.87 25.78 0 top
R104  0  [0402_CC]  127.89 33.78 270 top
R105  1K  [0402_CC]  121.92 32.38 90 top
R106  1K  [0402_CC]  121.92 33.92 90 top
R107  1K  [0402_CC]  127.89 32.26 270 top
R108  0  [0402_CC]  122.69 35.56 270 top
R109  10K  [0402_CC]  123.19 34.29 0 top
R110  1K  [0402_CC]  129.29 31.88 0 top
R111  0  [0402_CC]  123.69 35.56 270 top
R112  1K  [0402_CC]  124.46 33.92 270 top
R113  1K  [0402_CC]  124.46 32.38 90 top
R114  10K  [0402_CC]  121.67 55.12 180 top
R115  100  [0402_CC]  123.83 55.38 180 top
R116  75.0  [RC0805_OV]  126.24 57.66 90 top
R117  10K  [0402_CC]  121.67 56.34 180 top
R118  0  [0402_CC]  147.32 21.09 270 top
R119  0  [0402_CC]  140.46 21.09 270 top
R120  0  [0402_CC]  143 21.09 270 top
R121  0  [0402_CC]  136.14 21.09 270 top
R122  374  [RC0805_OV]  122.43 46.06 270 top
R123  93.1  [RC0603_OV]  126.36 45.86 90 top
R124  0  [0402_CC]  122.05 48.55 0 top
R125  0  [0402_CC]  124.46 46.62 180 top
R126  49.9  [RC0603_OV]  113.41 40.29 180 top
R127  49.9  [RC0603_OV]  110.62 40.29 0 top
R128  49.9  [RC0603_OV]  107.82 40.29 180 top
R129  49.9  [RC0603_OV]  105.03 40.29 0 top
R130  0  [0402_CC]  111.89 42.2 90 bottom
R131  1K  [0402_CC]  113.92 43.59 180 top
R132  1K  [0402_CC]  113.92 44.74 180 top
R133  6.49K  [0402_CC]  113.92 42.58 0 top
R134  4.7K  [0402_CC]  113.92 45.88 0 top
R135  1K  [0402_CC]  113.79 49.05 0 top
R136  1K  [0402_CC]  113.79 48.8 0 bottom
R137  1K  [0402_CC]  113.92 46.9 0 top
R138  4.7K  [RC0402_25]  113.92 47.91 0 top
R139  4.7K  [0402_CC]  113.78 50.2 0 top
R140  1K  [0402_CC]  103.5 46.64 180 top
R141  1K  [0402_CC]  111.76 51.59 90 top
R142  4.7K  [RC0402_25]  103.37 47.66 180 top
R143  1K  [0402_CC]  103.5 44.61 180 bottom
R144  4.7K  [0402_CC]  103.5 45.5 180 top
R145  4.7K  [0402_CC]  110.74 51.59 90 top
R146  1K  [0402_CC]  107.19 51.59 90 top
R147  4.7K  [RC0402_25]  108.2 51.73 90 top
R148  1K  [0402_CC]  103.5 44.48 180 top
R149  1K  [0402_CC]  103.5 43.47 180 top
R150  1K  [0402_CC]  112.9 51.56 90 top
R151  4.7K  [0402_CC]  109.45 51.59 90 top
R152  1K  [0402_CC]  106.17 51.59 90 top
R153  0  [0402_CC]  50.29 39.75 270 bottom
R154  0  [0402_CC]  52.5 41.15 270 bottom
R155  0  [0402_CC]  54.99 36.45 90 bottom
R156  0  [0402_CC]  53.59 37.34 90 bottom
R157  0  [0402_CC]  57.78 39.5 180 bottom
R158  0  [0402_CC]  57.68 37.57 90 bottom
R168  10K  [0402_CC]  55.58 43.43 270 bottom
R169  0  [0402_CC]  56.26 41.78 180 bottom
R170  10K  [0402_CC]  55.88 45.21 0 bottom
R171  10K  [0402_CC]  52.83 44.96 180 bottom
R172  10K  [0402_CC]  18.8 52.7 0 bottom
R173  10K  [0402_CC]  24.13 55.12 270 bottom
R174  10K  [0402_CC]  24.4 87 90 top
R175  10K  [0402_CC]  28.45 87.46 180 top
R176  10K  [0402_CC]  37.1 87 90 top
R177  10K  [0402_CC]  39.64 87 90 top
R178  10K  [0402_CC]  42.18 87 90 top
R179  100  [0402_CC]  44.72 87 90 top
R180  10K  [0402_CC]  34.56 87 270 top
R181  10K  [0402_CC]  32.02 87 270 top
R182  10K  [0402_CC]  21.86 87 270 top
R184  100K  [0402_CC]  32.06 54.48 270 bottom
R185  100K  [0402_CC]  39.25 61.34 180 top
R212  10K  [0402_CC]  125.48 64.26 90 top
R213  10K  [0402_CC]  121.28 83.95 180 top
R214  15K  [RC0402_25]  127.38 64.26 270 top
R215  10K  [0402_CC]  128.14 66.17 0 top
R216  1K  [0402_CC]  126.49 64.26 90 top
R217  0  [0402_CC]  128.91 10.92 90 top
R218  0  [0402_CC]  132.72 10.92 90 top
R219  10K  [0402_CC]  136.4 10.92 270 top
R220  0  [0402_CC]  137.79 10.92 90 top
R221  0  [0402_CC]  135.25 10.92 90 top
R222  0  [0402_CC]  133.99 10.92 90 top
R223  0  [0402_CC]  119.76 24.38 90 bottom
R224  0  [0402_CC]  130.18 10.92 90 top
R225  0  [0402_CC]  127.64 10.92 90 top
R226  0  [0402_CC]  121.67 20.32 180 bottom
R227  0  [0402_CC]  122.56 22.12 180 bottom
R228  0  [0402_CC]  122.56 23.11 180 bottom
R229  0  [0402_CC]  122.56 24.14 180 bottom
R230  10K  [0402_CC]  136.4 9.02 180 bottom
R232  10K  [0402_CC]  140.59 13.72 0 top
R234  10K  [0402_CC]  139.06 13.72 0 top
R235  1K  [0402_CC]  68.93 92 270 top
R236  1K  [0402_CC]  70.2 92 270 top
R237  1K  [0402_CC]  71.47 92 270 top
R238  1K  [0402_CC]  72.74 92 270 top
R239  1K  [0402_CC]  77.18 92 270 top
R240  1K  [0402_CC]  78.45 92 270 top
R241  1K  [0402_CC]  79.72 92 270 top
R242  1K  [0402_CC]  80.99 92 270 top
R243  1K  [0402_CC]  85.44 92 270 top
R244  1K  [0402_CC]  86.71 92 270 top
R245  1K  [0402_CC]  87.98 92 270 top
R246  1K  [0402_CC]  89.25 92 270 top
R247  10K  [0402_CC]  83.57 68.45 180 top
R248  10K  [0402_CC]  80.77 69.72 0 top
R249  10K  [0402_CC]  80.77 68.45 0 top
R250  10K  [0402_CC]  81.65 67.06 180 top
R251  10K  [0402_CC]  81.65 65.91 180 top
R252  10K  [0402_CC]  88.26 67.56 180 top
R253  10K  [0402_CC]  85.98 68.45 0 top
R254  10K  [0402_CC]  87.5 66.29 180 top
R255  10K  [0402_CC]  85.72 69.98 0 top
R256  10K  [0402_CC]  85.72 66.29 180 top
R257  10K  [0402_CC]  83.43 67.06 180 top
R258  10K  [0402_CC]  91.69 69.98 180 top
R259  10K  [0402_CC]  89.79 81.41 90 top
R260  10K  [0402_CC]  88.27 81.41 90 top
R261  10K  [0402_CC]  69.47 75.56 180 top
R262  10K  [0402_CC]  68.45 78.11 90 top
R263  0  [0402_CC]  67.18 78.61 0 top
R264  0  [0402_CC]  67.18 75.56 0 top
R265  10K  [0402_CC]  67.18 77.6 180 top
R266  10K  [0402_CC]  60.08 81.53 180 top
R267  0  [0402_CC]  67.18 76.58 0 top
R268  10K  [0402_CC]  60.96 71.25 90 top
R269  0  [0402_CC]  62.23 71.25 270 top
R270  4.7K  [RC0402_25]  55.5 75.56 180 top
R271  4.7K  [RC0402_25]  58.55 71.38 270 top
R272  0  [0402_CC]  55.37 76.97 180 top
R273  0  [0402_CC]  59.69 71.25 270 top
R275  0  [0402_CC]  133.61 15.83 180 top
R276  0  [0402_CC]  73.28 3.68 90 top
R277  0  [0402_CC]  74.3 3.68 90 top
R278  0  [0402_CC]  15.11 59.56 270 bottom
R279  0  [0402_CC]  16.38 58.55 270 bottom
R280  0  [0402_CC]  15.11 54.23 270 bottom
R281  0  [0402_CC]  17.02 56.13 270 bottom
R282  0  [0402_CC]  38.48 48.39 180 bottom
R283  0  [0402_CC]  41.27 62.36 180 top
R284  0  [0402_CC]  56.52 81.92 270 top
R285  0  [0402_CC]  81.16 50.29 0 bottom
R286  0  [0402_CC]  79.88 50.93 90 bottom
R287  0  [0402_CC]  90.42 53.47 180 top
R288  0  [0402_CC]  86.61 50.04 180 bottom
R289  0  [0402_CC]  117.35 32.77 270 bottom
R290  0  [0402_CC]  87.63 46.86 270 bottom
R291  0  [0402_CC]  88.77 46.86 90 bottom
R293  0  [0402_CC]  68.07 38.99 270 top
R294  10K  [0402_CC]  51.18 39.75 90 bottom
R301  0  [0402_CC]  52.58 18.39 90 top
R303  10K  [0402_CC]  71.63 56.9 180 top
R304  200K  [0402_CC]  57.53 9.53 0 top
R305  464K  [0402_CC]  57.15 10.79 270 top
R309  1K  [0402_CC]  102.62 49.4 0 bottom
R310  0  [0402_CC]  57.28 15.11 0 top
R311  0  [0402_CC]  57.28 16.13 0 top
R313  10K  [0402_CC]  23.11 55.12 90 bottom
R314  100K  [0402_CC]  92.71 68.45 180 top
R316  220  [RC0603_OV]  99.31 40.89 270 top
R320  0  [0402_CC]  24.13 57.4 90 bottom
R322  10K  [0402_CC]  103.5 42.04 270 top
R323  0  [0402_CC]  102.36 42.04 90 top
R324  1K  [0402_CC]  91.69 70.99 180 top
R325  1K  [0402_CC]  83.57 72.77 180 bottom
R326  100K  [0402_CC]  76.58 14.86 270 top
R328  0  [0402_CC]  83.06 11.3 0 top
R329  0  [0402_CC]  83.69 15.62 270 top
R332  100K  [0402_CC]  85.72 15.62 270 top
R333  10K  [0402_CC]  84.71 15.62 90 top
R334  0  [0402_CC]  87.76 15.62 270 top
R335  100K  [RC0402_25]  88.77 15.62 90 top
R336  0  [0402_CC]  86.36 20.83 90 top
R341  0  [0402_CC]  90.42 25.91 270 top
R342  100K  [RC0402_25]  91.44 25.91 90 top
R344  0  [0402_CC]  86.36 25.91 270 top
R346  100K  [0402_CC]  87.38 25.91 270 top
R348  10K  [0402_CC]  88.39 25.91 90 top
R349  100K  [0402_CC]  86.74 15.62 270 top
R350  100K  [0402_CC]  89.41 25.91 270 top
R351  100K  [RC0402_25]  128.14 67.56 180 top
R352  0  [0402_CC]  133.99 65.91 0 top
R353  0  [0402_CC]  137.16 65.91 180 top
R354  0  [0402_CC]  59.56 14.61 270 top
R355  0  [0402_CC]  44.45 16.38 180 top
R356  0  [0402_CC]  50.67 40.89 0 bottom
R357  0.02  [RC0603_OV]  37.21 43.05 180 top
R358  33K  [RC0402_25]  59.18 27.18 90 bottom
R359  33K  [RC0402_25]  61.21 27.81 180 bottom
R360  10K  [0402_CC]  58.29 24.51 90 bottom
R361  0  [0402_CC]  52.91 41.55 0 bottom
R362  0  [0402_CC]  54.99 37.21 90 bottom
R363  0  [0402_CC]  53.59 38.1 90 bottom
R364  0  [0402_CC]  57.02 39.5 180 bottom
R365  0  [0402_CC]  57.28 37.97 180 bottom
R366  0  [0402_CC]  54.23 41.2 270 bottom
R371  0  [0402_CC]  21.08 55.12 270 bottom
R372  0  [0402_CC]  22.1 55.12 270 bottom
R375  0  [0402_CC]  137.66 67.91 180 top
R376  0  [0402_CC]  137.66 68.79 180 top
R377  200K  [0402_CC]  145.29 84.2 0 top
R378  464K  [0402_CC]  143.64 84.2 0 top
R379  270  [RC0402_25]  137.67 69.72 180 top
R380  12.0K  [RC0402_25]  137.67 70.87 180 top
R381  12.0K  [RC0402_25]  123.44 75.06 0 top
R382  12.0K  [RC0402_25]  123.44 76.07 0 top
R383  100K  [0402_CC]  123.44 72.01 0 top
R387  2.2K  [RC0402_25]  123.44 78.49 0 top
R388  2.2K  [RC0402_25]  137.67 73.91 0 top
R389  2.2K  [RC0402_25]  137.67 71.88 0 top
R390  2.2K  [RC0402_25]  123.44 74.04 180 top
R391  2.2K  [RC0402_25]  123.44 79.5 180 top
R392  270  [RC0402_25]  137.67 72.9 0 top
R393  10K  [0402_CC]  124.59 91.31 90 top
R394  10K  [0402_CC]  146.05 89.92 180 top
R400  0  [0402_CC]  146.05 90.93 180 top
R401  180K  [RC0402_25]  142.62 86.11 90 top
R402  4.7K  [RC0402_25]  140.97 89.66 90 top
R410  0  [0402_CC]  141.48 86.11 90 top
R411  10K  [0402_CC]  118.62 91.19 0 top
R412  1K  [0402_CC]  128.91 87.88 180 top
R413  4.7K  [RC0402_25]  114.55 95.38 270 top
R414  2.2K  [RC0402_25]  112.52 92.2 270 top
R416  100  [RC0402_25]  95.5 96.9 90 top
R417  100  [RC0402_25]  96.39 96.9 90 top
R418  100K  [0402_CC]  98.04 93.6 270 top
R419  100K  [0402_CC]  110.62 94.49 270 top
R422  100K  [0402_CC]  92.71 88.27 270 top
R423  12.0K  [RC0402_25]  123.44 72.9 0 top
R424  0  [0402_CC]  52.83 44.07 0 bottom
R425  0  [0402_CC]  52.83 43.18 0 bottom
R426  0  [0402_CC]  56.46 43.43 270 bottom
R427  0  [0402_CC]  52.83 45.85 180 bottom
R428  0  [0402_CC]  82.42 80.26 90 top
SW1  EG2209A  [SW6_DPDT_11X6MM]  24.85 3.84 180 top
SW2  SPST PB  [SW4_PB_ESW_SM_P177]  52.22 5.08 270 top
SW3  SPST PB  [SW4_PB_ESW_SM_P177]  38.23 5.08 270 top
SW5  DHN-04  [97C04]  70.83 86.66 0 top
SW6  DHN-04  [97C04]  79.09 86.66 0 top
SW7  DHN-04  [97C04]  87.34 86.66 0 top
SW8  SPST PB  [SW4_PB_ESW_SM_P177]  45.09 71.12 90 top
SW9  SPST PB  [SW4_PB_ESW_SM_P177]  133.1 95.25 90 top
T1  TTWB1010L  [XFMR6_6P6X6P2]  131.44 57.92 180 top
T2  TTWB1010L  [XFMR6_6P6X6P2]  131.44 45.86 180 top
TP1  -  [TPAD_030]  14.86 12.95 90 top
TP2  5006  [TP_TH_063]  3.17 26.04 0 top
TP3  5006  [TP_TH_063]  60.45 90.3 0 top
TP4  5006  [TP_TH_063]  115.57 35.56 0 top
TP5  5006  [TP_TH_063]  71.75 13.34 0 top
TP6  TP_35MIL  [TESTPOINT_35MIL]  59.05 38.35 90 top
TP7  TP_35MIL  [TESTPOINT_35MIL]  39.5 13.46 0 top
TP8  TP_35MIL  [TESTPOINT_35MIL]  34.03 22.23 0 top
TP9  TP_35MIL  [TESTPOINT_35MIL]  39.5 42.04 0 top
TP10  TP_35MIL  [TESTPOINT_35MIL]  48.9 20.32 270 top
TP11  TP_35MIL  [TESTPOINT_35MIL]  74.37 56.64 0 top
TP12  TP_35MIL  [TESTPOINT_35MIL]  109.86 53.21 90 top
TP22  TP_35MIL  [TESTPOINT_35MIL]  73.79 43.94 0 top
TP23  TP_35MIL  [TESTPOINT_35MIL]  66.12 50.62 0 top
TP25  TP_35MIL  [TESTPOINT_35MIL]  84.45 62.23 0 top
TP26  TP_35MIL  [TESTPOINT_35MIL]  81.92 62.23 0 top
TP27  TP_35MIL  [TESTPOINT_35MIL]  48.9 52.58 0 top
TP28  TP_35MIL  [TESTPOINT_35MIL]  50.8 51.56 0 top
TP29  -  [TPAD_030]  144.02 91.06 180 top
TP30  -  [TPAD_030]  140.97 87.76 180 top
TVS1  ESD5B5.0ST1G  [DIODE2_SOD523]  12.19 22.1 180 top
TVS2  ESD5B5.0ST1G  [DIODE2_SOD523]  137.79 25.15 90 top
TVS3  ESD5B5.0ST1G  [DIODE2_SOD523]  141.85 25.91 180 top
TVS4  ESD5B5.0ST1G  [DIODE2_SOD523]  137.05 37.6 0 top
TVS5  ESD5B5.0ST1G  [DIODE2_SOD523]  147.32 26.17 90 top
U1  MIMXRT1052DVL6B  [BGA196_0P65_10X10MM]  58.42 55.24 0 top
U2  UM803RS  [SOT-23]  65.91 41.78 270 top
U3  MP2144GJ  [TSOT23_8_0P65_2X1]  34.42 17.03 0 top
U4  UM1750S-00  [SOT23-5_A]  54.36 10.79 0 top
U5  UM805RE  [SOT_143]  39.88 22.85 270 top
U6  UM1750S-00  [SOT23-5_A]  37.34 37.99 0 top
U7  UM1550S-18  [SOT23-3-1P95]  47.12 23.37 0 top
U8  UM1661  [SOT23_6_B]  96.65 66.68 90 top
U9  RClamp0854P.TCT  [SLP1616P6]  90.68 8.34 180 top
U11  RClamp0854P.TCT  [SLP1616P6]  80.01 8.34 180 top
U12  TJA1057GT/3  [SO8_1P27_4X5]  74.69 19.94 270 top
U13  WM8960  [QFN32_S142EP]  127.64 24.9 270 top
U14  NC7WV04L6X  [MICROPAK_6P]  123.83 57.29 90 top
U15  NL17SZ126DF  [SC-70]  122.43 51.44 270 top
U16  KSZ8081RNB  [QFN32_0P5_EP3P3]  108.7 45.5 90 top
U17  SRV05-4  [SOT23_S6]  109.35 35.08 0 top
U19  S26KS512SDPBHI02  [PBGA24_1_6X8MM]  54.74 39.76 0 top
U20  IS42S16160J-6BLI  [VFBGA54_8X8]  33.66 57.78 270 top
U31  NX5P3090UK  [WLCSP12_0P4_1P38X1P68MM_SMDP]  131.32 66.17 90 top
U32  FXOS8700CQ  [QFN5X3_0P5_3X3]  60.96 77.47 0 top
U33  IS25WP064AJBLE  [SO8-25X75-200]  57.91 26.54 90 top
U34  NX5P3090UK  [WLCSP12_0P4_1P38X1P68MM_SMDP]  86.23 12.32 0 top
U35  NX5P3090UK  [WLCSP12_0P4_1P38X1P68MM_SMDP]  89.03 22.1 0 top
U37  NX3P191UK  [WLCSP4_0P4_0P8X0P8_SMDP]  28.32 38.61 180 top
U38  LPC4322JET100  [FBGA100_0P8_9X9]  130.81 74.17 90 top
U39  PRTR5V0U2X  [SOT143B]  142.91 72.5 0 top
U40  UM1750S-00  [SOT23-5_A]  144.15 81.15 90 top
U44  NTSX2102GU8H  [XQFN8_1P45X1P25MM]  143.26 88.9 180 top
U45  NTS0102  [TSSOP8_A]  116.97 95.38 270 top
U46  74LVC1T45GW,125  [SOT-363_0P65_SMT]  112.52 95.38 270 top
U48  74LVC2T45DC  [SSOP8_DCU]  96.01 93.22 0 top
U49  74LVC1T45GW,125  [SOT-363_0P65_SMT]  94.61 88.27 270 top
Y1  24MHZ  [XTLOSC4_3P2X2P5MM_SM]  70.54 47.16 270 top
Y2  32.768KHZ  [XTAL2-3P2X1P5-SM]  63.88 45.21 180 top
Y4  12MHZ  [XTL2_11P6X4P85_SM]  117.6 70.87 270 top

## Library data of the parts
C1-C4 C6-C27 C29-C37 C39-C92 C98-C101 C103-C131 C133-C143 C148-C150 C160-C171 C184-C223 C229-C238 C242 C243 C246-C249 C252 C254 C255 C257-C268 C270 C272-C278 = CAP_NP
C5 C93 C97 C102 C132 C239-C241 = CAP_NP: tolerance: 20%
C144-C147 = CAP_NP: tolerance: 5%
C244 C245 = CAP_NP: room: ATLAS-AP
D1 = ZDIODE
D2 D4-D9 D12-D14 D17 = DIODE_SCHTKY
D3 = LED_DUAL_SEP_RG
D10 = DIODE
D11 = DIODE_NUP2105L
D18 D20 D21 = LED
FL1 = FILTER_4P
H1-H4 = SPACER
J1 J34 = CONN_HDR_5X2
J2 = PHONEJACK-3
J3-J7 J13 J15-J17 J26 J36-J38 J42 J44-J50 = CONN_HDR_2X1
J8 = MODULE_LCD_46P
J9 J10 J41 = USB_MINI_AB_RECEPTACLE
J11 J43 = CONN_HDR_3X1
J12 = CONN_AUDIOJACK_6P
J14 J18 = KLPX0848A
J19 = RJ45_HR961160C_12P
J21 = CONN_HDR_10X2
J22 J25 = CONN_HDR_8X1
J23 = CONN_HDR_6X1
J24 = CONN_HDR_10X1
J35 = CON_1X24
J39 = CON8_SDCARD_DETECT
JP1 = JUMPER1x2
L1 L3 = IND_FERRITE
L2 = IND: tolerance: 30%
L4 L6 L7 L9 L14 L22-L24 = BEAD: tolerance: 25%
L5 L8 = DLW43: signal model: DLW43_IND4_CHOKE_0805_DISCRETE__90OHM
L10-L13 L17-L20 = INDUCTOR_FERRITE
P1 = MIC_POM
Q1 Q2 = FDMA530PZ
Q3 = PNP
Q4 = NMOS_2N7002BKW_3P
Q6 = MOSFET_P
Q9 Q15 = 2SK3018
R1 R2 R6 R7 R16 R18-R21 R25 R28-R36 R38 R39 R41-R49 R52 R54 R55 R57 R61-R66 R71 R85 R86 R88-R90 R92-R108 R110-R113 R115 R118-R121 R124 R125 R130-R137 R139-R141 R143-R146 R148-R152 R169 R172 R174-R182 R184 R185 R212 R216-R230 R232 R234-R246 R261-R273 R275-R277 R284-R291 R293 R301 R304 R305 R309-R311 R314 R316 R320 R323-R325 R328 R329 R333-R336 R341 R342 R344 R348 R351-R355 R358 R359 R371 R372 R377-R382 R392 R393 R400 R410-R412 R416 R417 R423-R428 = RES
R3-R5 R8-R11 R27 R59 R60 R67 R109 R114 R117 R138 R142 R147 R168 R170 R171 R173 R213 R215 R247-R260 R294 R303 R313 R322 R326 R332 R346 R349 R350 R360 R383 R387-R391 R394 R402 R413 R414 R418 R419 R422 = RES: tolerance: 5%
R12-R15 R24 R116 R122 R123 R126-R129 R214 R357 R401 = RES: tolerance: 1%
R68 R69 R83 R84 R87 R91 = RES: signal model: RES_0402_CC_DISCRETE_0.45_MM_47_0
R153-R158 R278-R283 R356 R361-R366 R375 R376 = RES: signal model: RES_0402_CC_DISCRETE_0_0
SW1 = SW_DPDT_3
SW2 SW3 SW8 SW9 = SW_PB_ESW
SW5-SW7 = SW_DIP-4_SM
T1 T2 = XFMR: room: SPDIF
TP1 TP29 TP30 = TestLoop
TP2-TP5 = TEST_POINT
TP6-TP12 TP22 TP23 TP25-TP28 = T POINT R: Tolerance: TOLERANCE; User Part Number: 510-75618
TVS1-TVS5 = DIODE_TVS_BIDIR
U1 = IMX6_BGA_196P
U2 = SGM803_SOT23-3P
U3 = MP2144GJ_TSOT23_8P
U4 U6 U40 = UM1750S-00_5P
U5 = UM805_4P
U7 = MCP1700
U8 = UM1661_SOT23_6P
U9 U11 = RCLAMP1654P_NEW
U12 = TJA1057GT3_8P
U13 = WM8960_QFN_33P
U14 = 74AUP2G06GW
U15 = 100201_SO-1
U16 = KSZ8081RNB_32P
U17 = SRV05-4
U19 = S26KS512SDPBHI02
U20 = MT48LC16M16A2B4_BGA54
U31 U34 U35 = NX5P3090UK_WLCSP12
U32 = FXOS8700CQ_QFN_16P
U33 = 25WP_8P
U37 = ADP172_CSP_4P
U38 = LPC432_BGA_100P
U39 = PRTR5V0U2X
U44 = NTSX2102GU8H_8P
U45 = NTB0102_8P
U46 U49 = 74LVCH1T45_6P
U48 = 74LVC2T45DC_8P
Y1 = CRYSTAL_JXS63
Y2 = CRYSTAL
Y4 = XTAL

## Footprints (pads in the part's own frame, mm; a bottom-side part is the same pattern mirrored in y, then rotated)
97C04
  rect 0.762x1.245 smd: 1(-1.905,-3.073) 2(-0.635,-3.073) 3(0.635,-3.073) 4(1.905,-3.073) 5(1.905,3.073) 6(0.635,3.073) 7(-0.635,3.073) 8(-1.905,3.073)
100MIL_TH
  rect 1.422x1.422 hole 0.914: 1(0,0)
  round 1.422 hole 0.914: 2(2.54,0)
0402_CC
  rect 0.457x0.508 smd: 1(-0.375,0) 2(0.375,0)
0603_CC
  rect 0.711x0.838 smd: 1(-0.65,0) 2(0.65,0)
0805_CC
  rect 0.94x1.346 smd: 1(-0.78,0) 2(0.78,0)
BGA196_0P65_10X10MM
  round 0.254 smd: A1(-4.225,4.225) A2(-3.575,4.225) A3(-2.925,4.225) A4(-2.275,4.225) A5(-1.625,4.225) A6(-0.975,4.225) A7(-0.325,4.225) A8(0.325,4.225) A9(0.975,4.225) A10(1.625,4.225) A11(2.275,4.225) A12(2.925,4.225) A13(3.575,4.225) A14(4.225,4.225) B1(-4.225,3.575) B2(-3.575,3.575) B3(-2.925,3.575) B4(-2.275,3.575) B5(-1.625,3.575) B6(-0.975,3.575) B7(-0.325,3.575) B8(0.325,3.575) B9(0.975,3.575) B10(1.625,3.575) B11(2.275,3.575) B12(2.925,3.575) B13(3.575,3.575) B14(4.225,3.575) C1(-4.225,2.925) C2(-3.575,2.925) C3(-2.925,2.925) C4(-2.275,2.925) C5(-1.625,2.925) C6(-0.975,2.925) C7(-0.325,2.925) C8(0.325,2.925) C9(0.975,2.925) C10(1.625,2.925) C11(2.275,2.925) C12(2.925,2.925) C13(3.575,2.925) C14(4.225,2.925) D1(-4.225,2.275) D2(-3.575,2.275) D3(-2.925,2.275) D4(-2.275,2.275) D5(-1.625,2.275) D6(-0.975,2.275) D7(-0.325,2.275) D8(0.325,2.275) D9(0.975,2.275) D10(1.625,2.275) D11(2.275,2.275) D12(2.925,2.275) D13(3.575,2.275) D14(4.225,2.275) E1(-4.225,1.625) E2(-3.575,1.625) E3(-2.925,1.625) E4(-2.275,1.625) E5(-1.625,1.625) E6(-0.975,1.625) E7(-0.325,1.625) E8(0.325,1.625) E9(0.975,1.625) E10(1.625,1.625) E11(2.275,1.625) E12(2.925,1.625) E13(3.575,1.625) E14(4.225,1.625) F1(-4.225,0.975) F2(-3.575,0.975) F3(-2.925,0.975) F4(-2.275,0.975) F5(-1.625,0.975) F6(-0.975,0.975) F7(-0.325,0.975) F8(0.325,0.975) F9(0.975,0.975) F10(1.625,0.975) F11(2.275,0.975) F12(2.925,0.975) F13(3.575,0.975) F14(4.225,0.975) G1(-4.225,0.325) G2(-3.575,0.325) G3(-2.925,0.325) G4(-2.275,0.325) G5(-1.625,0.325) G6(-0.975,0.325) G7(-0.325,0.325) G8(0.325,0.325) G9(0.975,0.325) G10(1.625,0.325) G11(2.275,0.325) G12(2.925,0.325) G13(3.575,0.325) G14(4.225,0.325) H1(-4.225,-0.325) H2(-3.575,-0.325) H3(-2.925,-0.325) H4(-2.275,-0.325) H5(-1.625,-0.325) H6(-0.975,-0.325) H7(-0.325,-0.325) H8(0.325,-0.325) H9(0.975,-0.325) H10(1.625,-0.325) H11(2.275,-0.325) H12(2.925,-0.325) H13(3.575,-0.325) H14(4.225,-0.325) J1(-4.225,-0.975) J2(-3.575,-0.975) J3(-2.925,-0.975) J4(-2.275,-0.975) J5(-1.625,-0.975) J6(-0.975,-0.975) J7(-0.325,-0.975) J8(0.325,-0.975) J9(0.975,-0.975) J10(1.625,-0.975) J11(2.275,-0.975) J12(2.925,-0.975) J13(3.575,-0.975) J14(4.225,-0.975) K1(-4.225,-1.625) K2(-3.575,-1.625) K3(-2.925,-1.625) K4(-2.275,-1.625) K5(-1.625,-1.625) K6(-0.975,-1.625) K7(-0.325,-1.625) K8(0.325,-1.625) K9(0.975,-1.625) K10(1.625,-1.625) K11(2.275,-1.625) K12(2.925,-1.625) K13(3.575,-1.625) K14(4.225,-1.625) L1(-4.225,-2.275) L2(-3.575,-2.275) L3(-2.925,-2.275) L4(-2.275,-2.275) L5(-1.625,-2.275) L6(-0.975,-2.275) L7(-0.325,-2.275) L8(0.325,-2.275) L9(0.975,-2.275) L10(1.625,-2.275) L11(2.275,-2.275) L12(2.925,-2.275) L13(3.575,-2.275) L14(4.225,-2.275) M1(-4.225,-2.925) M2(-3.575,-2.925) M3(-2.925,-2.925) M4(-2.275,-2.925) M5(-1.625,-2.925) M6(-0.975,-2.925) M7(-0.325,-2.925) M8(0.325,-2.925) M9(0.975,-2.925) M10(1.625,-2.925) M11(2.275,-2.925) M12(2.925,-2.925) M13(3.575,-2.925) M14(4.225,-2.925) N1(-4.225,-3.575) N2(-3.575,-3.575) N3(-2.925,-3.575) N4(-2.275,-3.575) N5(-1.625,-3.575) N6(-0.975,-3.575) N7(-0.325,-3.575) N8(0.325,-3.575) N9(0.975,-3.575) N10(1.625,-3.575) N11(2.275,-3.575) N12(2.925,-3.575) N13(3.575,-3.575) N14(4.225,-3.575) P1(-4.225,-4.225) P2(-3.575,-4.225) P3(-2.925,-4.225) P4(-2.275,-4.225) P5(-1.625,-4.225) P6(-0.975,-4.225) P7(-0.325,-4.225) P8(0.325,-4.225) P9(0.975,-4.225) P10(1.625,-4.225) P11(2.275,-4.225) P12(2.925,-4.225) P13(3.575,-4.225) P14(4.225,-4.225)
CASE403D_02
  rect 2.007x2.007 smd: A(2,0) C(-2,0)
CC0402_25
  round 0.635 smd: 1(-0.508,0) 2(0.508,0)
CC0603_OV
  oval 0.889x1.143 smd: 1(-0.762,0) 2(0.762,0)
CC1206_OV
  oval 1.016x1.778 smd: 1(-1.524,0) 2(1.524,0)
CC1210
  rect 1.778x2.845 smd: 1(-1.397,0) 2(1.397,0)
CON2_RCA_RA_TH
  oval 2x3.65 hole 1.2x2.2: 1(0,0)
  oval 3.302x1.651 hole 2.007x1.016: 2(4.5,0)
CON3_PWR_TH
  oval 4.013x1.549 hole 3.5x0.8: 1(0,0)
  oval 3.759x1.549 hole 2.997x0.787: 2(0,-6)
  oval 1.549x3.759 hole 0.787x2.997: 3(4.8,-2.5)
CON6_AUDJACK_RA_TH
  round 0.254 hole 1.499 unplated: (0.4,2.7) (7.4,2.7)
  oval 2.108x1.092 hole 1.499x0.508: 1(0,0) 4(0,5.1)
  rect 1.6x2.007 smd: 2(9.4,6.1) 3(9.4,-0.7) 5(6.3,6.1) 6(6.3,-0.7)
CON12_RJ45_1P02_SM
  round 0.254 hole 2.997 unplated: (-6.35,9.96) (6.35,9.96)
  rect 0.813x4.597 smd: 1(-6.61,-9.96) 2(-4.77,-9.96) 11(4.77,-9.96) 12(6.61,-9.96)
  rect 0.61x4.597 smd: 3(-3.57,-9.96) 4(-2.55,-9.96) 5(-1.53,-9.96) 6(-0.51,-9.96) 7(0.51,-9.96) 8(1.53,-9.96) 9(2.55,-9.96) 10(3.57,-9.96)
  custom 0.75x0.75 smd: 13(-8.92,9.96) 14(8.92,9.96)
CON_1X8_SKT_2P54_TH
  rect 1.702x1.702 hole 1.016: 1(0,0)
  round 1.702 hole 1.016: 2(0,-2.54) 3(0,-5.08) 4(0,-7.62) 5(0,-10.16) 6(0,-12.7) 7(0,-15.24) 8(0,-17.78)
CON_SDCARD_95220
  rect 0.813x1.499 smd: 1(-1.94,3.267) 2(-0.84,2.867) 3(0.26,3.267) 4(1.36,3.468) 5(2.46,3.267) 6(3.56,3.468) 7(4.66,3.267) 8(5.76,3.267)
  rect 0.991x0.94 smd: 9(3.56,-7.368)
  rect 1.397x1.905 smd: SH1(6.6,6.187) SH2(-6.6,7.107)
  rect 1.295x1.422 smd: SH3(4.95,-7.092) SH4(-0.75,-7.092)
CON_SKT1X6_TH
  rect 1.524x1.524 hole 1.041: 1(0,0)
  round 1.524 hole 1.041: 2(0,-2.54) 3(0,-5.08) 4(0,-7.62) 5(0,-10.16) 6(0,-12.7)
CON_SKT1X10_TH
  rect 1.651x1.651 hole 1.016: 1(0,0)
  round 1.651 hole 1.016: 2(0,-2.54) 3(0,-5.08) 4(0,-7.62) 5(0,-10.16) 6(0,-12.7) 7(0,-15.24) 8(0,-17.78) 9(0,-20.32) 10(0,-22.86)
CON_USB5_MICROAB_0P65_SM
  round 0.254 hole 0.559 unplated: (-2,2.115) (2,2.115)
  rect 0.406x1.346 smd: 1(-1.3,2.64) 2(-0.65,2.64) 3(0,2.64) 4(0.65,2.64) 5(1.3,2.64)
  rect 1.905x1.905 smd: S1(-3.95,-0.035) S2(3.95,-0.035) S3(-1.2,-0.035) S4(1.2,-0.035)
DIODE2_SOD523
  rect 0.61x0.813 smd: 1(-0.85,0) 2(0.85,0)
FBGA100_0P8_9X9
  round 0.406 smd: A1(-3.6,3.6) A2(-2.8,3.6) A3(-2,3.6) A4(-1.2,3.6) A5(-0.4,3.6) A6(0.4,3.6) A7(1.2,3.6) A8(2,3.6) A9(2.8,3.6) A10(3.6,3.6) B1(-3.6,2.8) B2(-2.8,2.8) B3(-2,2.8) B4(-1.2,2.8) B5(-0.4,2.8) B6(0.4,2.8) B7(1.2,2.8) B8(2,2.8) B9(2.8,2.8) B10(3.6,2.8) C1(-3.6,2) C2(-2.8,2) C3(-2,2) C4(-1.2,2) C5(-0.4,2) C6(0.4,2) C7(1.2,2) C8(2,2) C9(2.8,2) C10(3.6,2) D1(-3.6,1.2) D2(-2.8,1.2) D3(-2,1.2) D4(-1.2,1.2) D5(-0.4,1.2) D6(0.4,1.2) D7(1.2,1.2) D8(2,1.2) D9(2.8,1.2) D10(3.6,1.2) E1(-3.6,0.4) E2(-2.8,0.4) E3(-2,0.4) E4(-1.2,0.4) E5(-0.4,0.4) E6(0.4,0.4) E7(1.2,0.4) E8(2,0.4) E9(2.8,0.4) E10(3.6,0.4) F1(-3.6,-0.4) F2(-2.8,-0.4) F3(-2,-0.4) F4(-1.2,-0.4) F5(-0.4,-0.4) F6(0.4,-0.4) F7(1.2,-0.4) F8(2,-0.4) F9(2.8,-0.4) F10(3.6,-0.4) G1(-3.6,-1.2) G2(-2.8,-1.2) G3(-2,-1.2) G4(-1.2,-1.2) G5(-0.4,-1.2) G6(0.4,-1.2) G7(1.2,-1.2) G8(2,-1.2) G9(2.8,-1.2) G10(3.6,-1.2) H1(-3.6,-2) H2(-2.8,-2) H3(-2,-2) H4(-1.2,-2) H5(-0.4,-2) H6(0.4,-2) H7(1.2,-2) H8(2,-2) H9(2.8,-2) H10(3.6,-2) J1(-3.6,-2.8) J2(-2.8,-2.8) J3(-2,-2.8) J4(-1.2,-2.8) J5(-0.4,-2.8) J6(0.4,-2.8) J7(1.2,-2.8) J8(2,-2.8) J9(2.8,-2.8) J10(3.6,-2.8) K1(-3.6,-3.6) K2(-2.8,-3.6) K3(-2,-3.6) K4(-1.2,-3.6) K5(-0.4,-3.6) K6(0.4,-3.6) K7(1.2,-3.6) K8(2,-3.6) K9(2.8,-3.6) K10(3.6,-3.6)
FPC1X24_0P5_16P6X5P35
  rect 1.803x2.007 smd: (-7.55,0.5) (7.55,0.5)
  rect 0.305x1.245 smd: 1(-5.75,3.175) 2(-5.25,3.175) 3(-4.75,3.175) 4(-4.25,3.175) 5(-3.75,3.175) 6(-3.25,3.175) 7(-2.75,3.175) 8(-2.25,3.175) 9(-1.75,3.175) 10(-1.25,3.175) 11(-0.75,3.175) 12(-0.25,3.175) 13(0.25,3.175) 14(0.75,3.175) 15(1.25,3.175) 16(1.75,3.175) 17(2.25,3.175) 18(2.75,3.175) 19(3.25,3.175) 20(3.75,3.175) 21(4.25,3.175) 22(4.75,3.175) 23(5.25,3.175) 24(5.75,3.175)
HDR102
  rect 1.524x1.524 hole 1.016: 1(0,0)
  round 1.524 hole 1.016: 2(0,-2.54)
HDR103
  rect 1.524x1.524 hole 1.016: 1(0,0)
  round 1.524 hole 1.016: 2(0,-2.54) 3(0,-5.08)
HDR205
  rect 1.676x1.676 hole 1.016: 1(0,0)
  round 1.676 hole 1.016: 2(2.54,0) 3(0,-2.54) 4(2.54,-2.54) 5(0,-5.08) 6(2.54,-5.08) 7(0,-7.62) 8(2.54,-7.62) 9(0,-10.16) 10(2.54,-10.16)
